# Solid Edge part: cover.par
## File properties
Author: f_grande
Template: Normal.par
Last saved by: f_grande
Revision: 3
Application: Solid Edge
Densità: 1385,000 kg/m^3
Precisione: 0,990
Tipo di contenuto documento: 0
Material: Plexiglas
Stile della faccia: Bianco (vetro)
Stile di riempimento: ANSI34(Plastica)
Stile virtuale: Marroncino (lucido)
Coef. of Thermal Exp: 0.0
Thermal Conductivity: 1.5
Specific Heat: 0.0
Modulus of Elasticity: 2757902.8
Poisson's Ratio: 0.4
Yield Stress: 6894757.0
Ultimate Stress: 0.0
Elongation: 0.0
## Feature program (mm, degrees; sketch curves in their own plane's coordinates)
sketch for "unnamed Protrusion 1" plane through (0, 0, 0) normal (0, 0, 1) x-axis (1, 0, 0)
  line (-23.5, 23.5) -> (23.5, 23.5)
  line (23.5, 23.5) -> (23.5, -23.5)
  line (23.5, -23.5) -> (-23.5, -23.5)
  line (-23.5, -23.5) -> (-23.5, 23.5)
  dimension (linear) = 23.5
  dimension (linear) = 23.5
extrude "unnamed Protrusion 1" add finite 3 along +normal
fillet "Rotondo_1" radius 3
sketch for "ExtrudedCutout_1" #1 plane through (0, 0, 3) normal (0, 0, 1) x-axis (1, 0, 0)
  circle centre (-23.5692, 0) radius 3.5
sketch for "ExtrudedCutout_1" #2 plane through (0, 0, 3) normal (0, 0, 1) x-axis (1, 0, 0)
  circle centre (23.5, 0) radius 3.5
extrude "ExtrudedCutout_1" cut finite 135 along -normal
sketch for "ExtrudedProtrusion_2" plane through (0, 0, 3) normal (0, 0, 1) x-axis (1, 0, 0)
  circle centre (-14, 14) radius 3.5
extrude "ExtrudedProtrusion_2" add finite 3.5 along +normal
pattern "unnamed Pattern 1" of "ExtrudedProtrusion_2"
pattern "unnamed Pattern 2"
fillet "Rotondo_2" radius 3.5
chamfer "Smusso_1" setback 1.5
thinwall "Thinwall_1"  Thickness = 1.5 mm
sketch for "ExtrudedCutout_2" plane through (0, 0, 3) normal (0, 0, 1) x-axis (-1, 0, 0)
extrude "ExtrudedCutout_2" cut finite 135 along -normal
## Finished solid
Body 1: solid body, 83 faces, 160 edges, 80 vertices.
  Faces by surface: sphere 32, plane 31, cylinder 12, cone 8
  Edges by curve: line 88, circle 64, ellipse 8
Bounding box of the edges (mm; curved faces can reach further): 47.000 x 47.000 x 3.000, from (-23.5, -23.5, 0) to (23.5, 23.5, 3).
Cylindrical faces by radius (mm): R1.5 x4, R3 x4, R3.5 x2, R5 x2
Conical faces (half-angle, radius in mm at the cone's reference point): 45 deg R0.4393 x4, 45 deg R1.5 x4
Spherical faces by radius (mm): R2 x16, R3.5 x16
Planar faces by outward normal: +x 5, +y 3, +z 1, -x 5, -y 3, -z 2, oblique 12
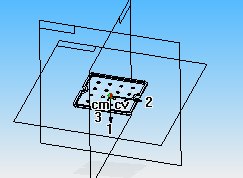
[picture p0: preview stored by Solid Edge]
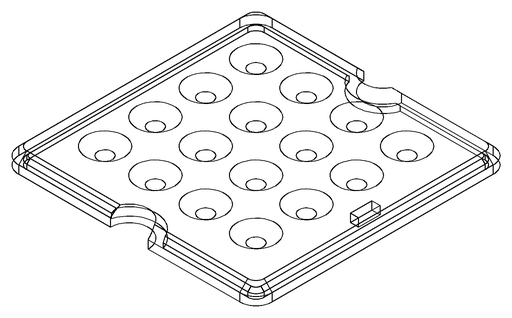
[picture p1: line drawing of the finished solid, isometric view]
